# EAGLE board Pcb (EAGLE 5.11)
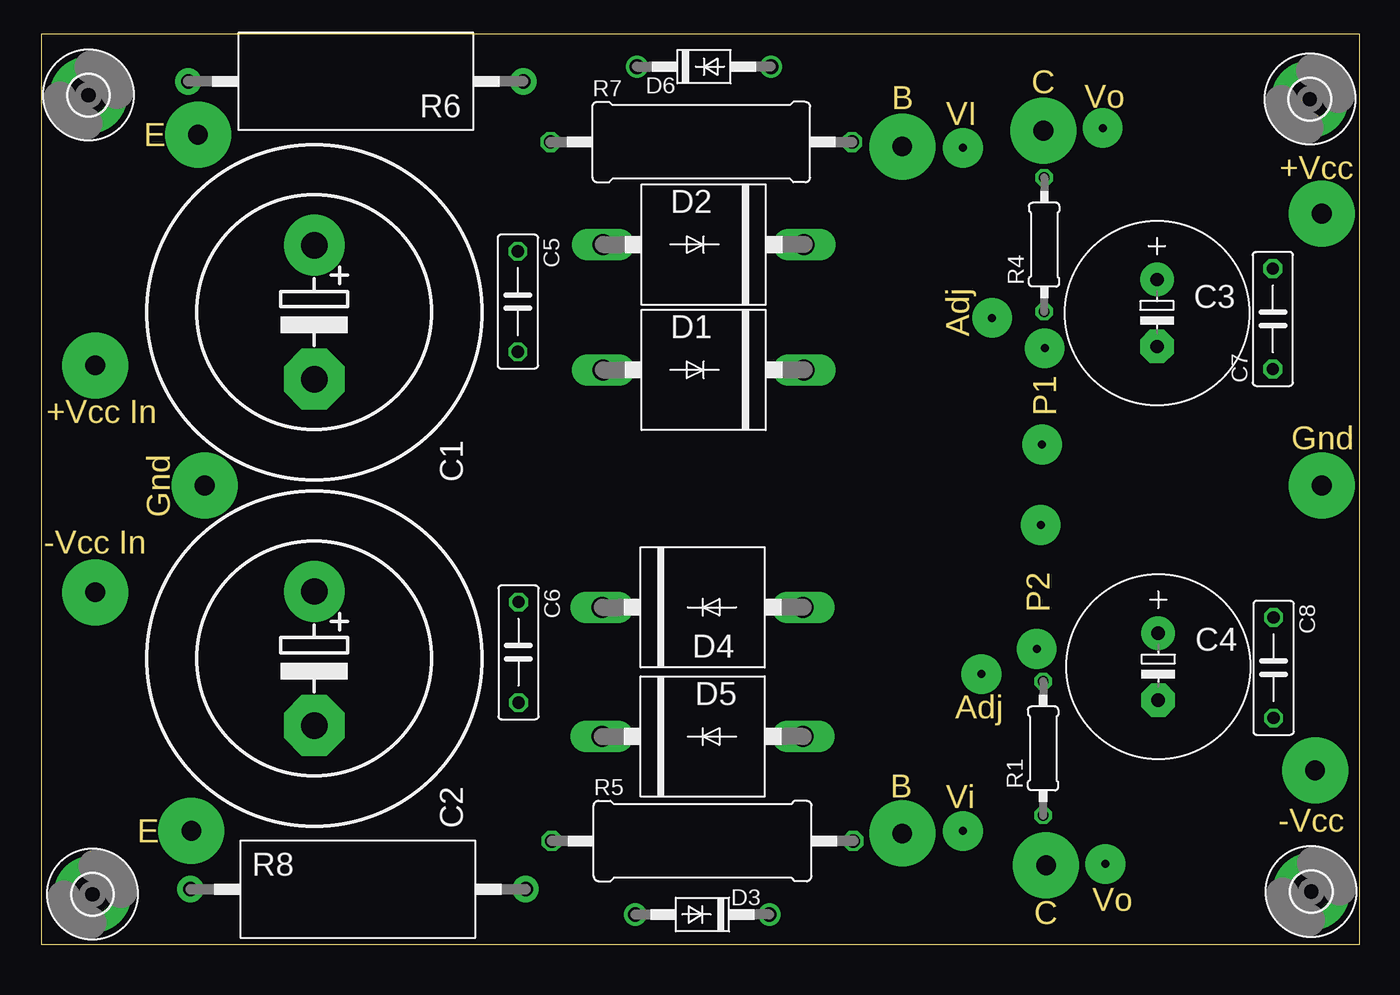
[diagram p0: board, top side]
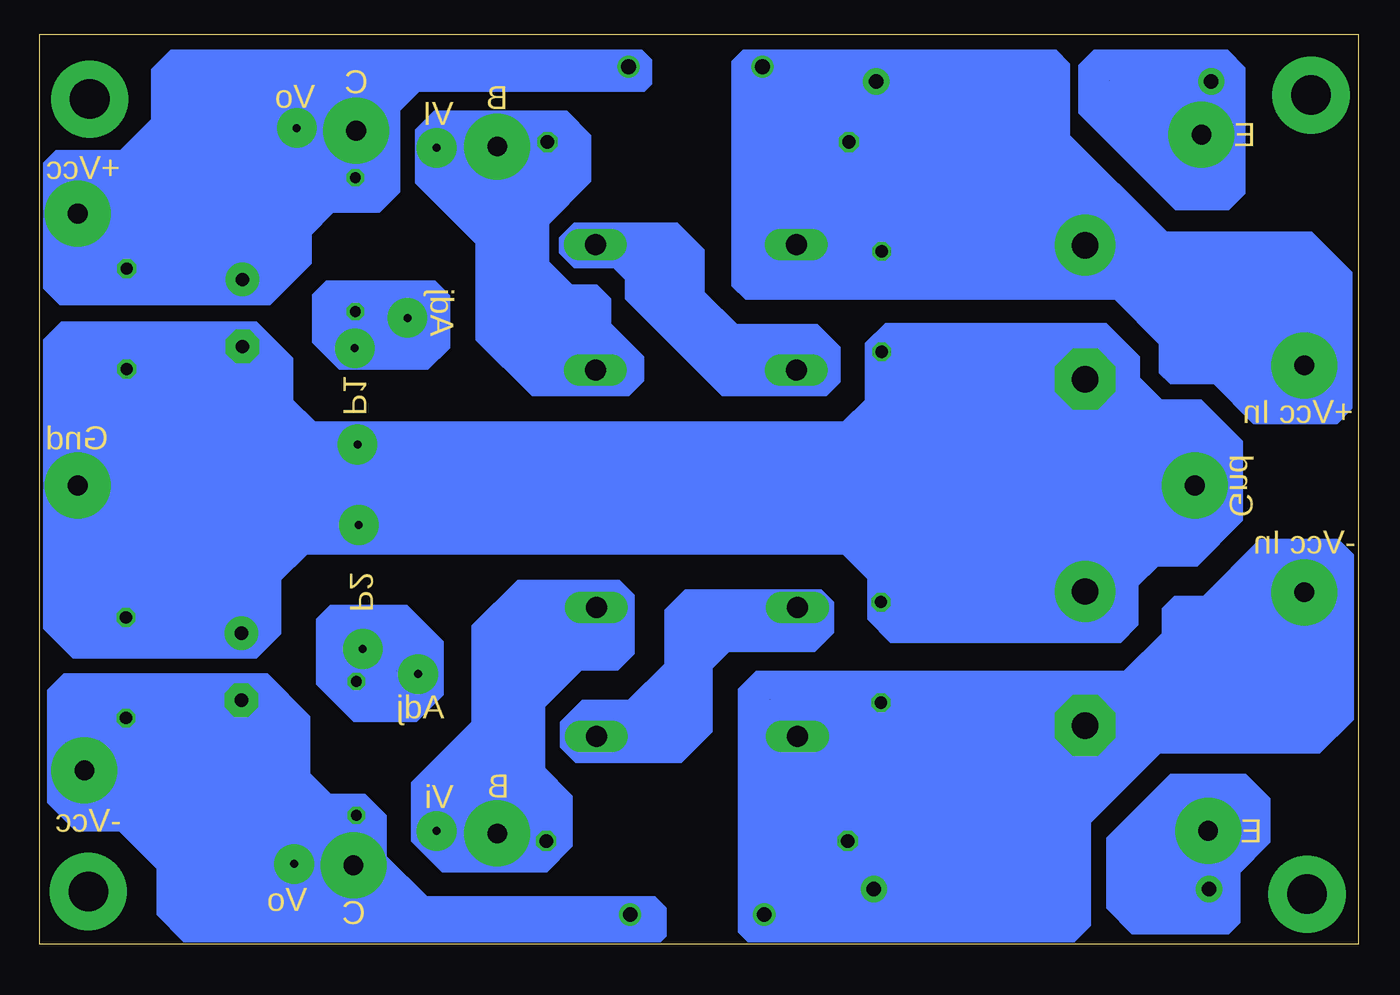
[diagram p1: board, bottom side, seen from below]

Size 100 x 69 mm. Coordinates in mm from the lower left corner, seen from the top.
Outline: 0,0 100,0 100,69 0,69 0,0
Copper layers (1*16): Top 0.035mm / dielectric 1.5mm / Bottom 0.035mm
Design rules "default": minimum track width 10mil, minimum drill 24mil, track to track 8mil, track to pad 8mil, pad to pad 8mil, via to via 8mil, smd to smd 8mil, copper to edge 40mil, drill to drill 8mil, minimum pad ring 10mil, minimum via ring 8mil, stop-mask expansion 4mil, vias tented up to drill 0mil, thermal gap 10mil

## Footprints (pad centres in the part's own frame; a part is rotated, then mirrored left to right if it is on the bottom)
EB25D = drill 2.007 pad 4.597 round: + -5.08,0 | drill 2.007 pad 4.597 octagon: - 5.08,0
E5-13 = drill 1.016 pad 2.54 round: + -2.54,0 | drill 1.016 pad 2.54 octagon: - 2.54,0
C075-032X103 = drill 0.914 octagon: 1 -3.81,0; 2 3.81,0
P6-15 = drill 1.6 long: A 7.62,0; C -7.62,0
DO41-10 = drill 1.118 round: A 5.08,0; C -5.08,0
3,0-PAD = drill 3 pad 5.842 round: B3,0 0,0
0207/10 = drill 0.813 octagon: 1 -5.08,0; 2 5.08,0
0617/22 = drill 1.016 octagon: 1 -11.43,0; 2 11.43,0
AC05 = drill 1.1 pad 2 round: 1 -12.7,0; 2 12.7,0

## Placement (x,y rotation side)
C1  4,7m  [EB25D]  20.72,47.94 270 top
C2  4,7m  [EB25D]  20.72,21.68 270 top
C3  1m  [E5-13]  84.61,47.87 270 top
C4  1m  [E5-13]  84.71,21.06 270 top
C5  100n  [C075-032X103]  36.15,48.74 270 top
C6  100n  [C075-032X103]  36.2,22.14 270 top
C7  100n  [C075-032X103]  93.4,47.43 90 top
C8  100n  [C075-032X103]  93.45,20.97 270 top
D1  1N5408  [P6-15]  50.24,43.56 180 top
D2  1N5408  [P6-15]  50.24,53.06 180 top
D3  1N4007  [DO41-10]  50.14,2.26 180 top
D4  1N5408  [P6-15]  50.16,25.56 0 top
D5  1N5408  [P6-15]  50.16,15.76 0 top
D6  1N4007  [DO41-10]  50.26,66.56 0 top
E$1  [3,0-PAD]  3.6,64.4 0 top
E$2  [3,0-PAD]  3.9,3.8 0 top
E$3  [3,0-PAD]  96.3,4 0 top
E$4  [3,0-PAD]  96.2,64.1 0 top
R1  2k2  [0207/10]  75.98,14.86 90 top
R4  2k2  [0207/10]  76.06,53.06 90 top
R5  10/2W  [0617/22]  50.16,7.84 0 top
R6  0.22/5W  [AC05]  23.86,65.44 0 top
R7  10/2W  [0617/22]  50.06,60.84 0 top
R8  0.22/5W  [AC05]  24.04,4.18 180 top

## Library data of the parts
C1-C8 R1 R4 R5 R7 = resistor
D1-D6 = diode
E$1-E$4 = holes
R6 R8 = resistor-power

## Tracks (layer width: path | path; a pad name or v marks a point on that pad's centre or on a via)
S$1
  Bottom 0.5: 9,38.1 9,32.2 12.3,28.9 15.3,28.9 16.9,27.3 16.9,24.3 18.1,23.1 35.4,23.1 37,24.7 37,27.8 39,29.8 79.8,29.8 81.9,27.7 81.9,23.6 83.6,21.9 97.4,21.9 99.5,24 99.5,31.9 99.5,32.2 99.5,45.8 98.3,47 83.6,47 81,44.4 81,41.2 79.2,39.4 39,39.4 37.2,41.2 37.2,45.5 35.8,46.9 19.2,46.9 16.8,44.5 16.8,42.9 15,41.1 12,41.1 9,38.1
S$2  (via drill 1.5 pad 5)
  other vias: 11.9,61.4 4.1,43.9 4.1,26.7 11.4,8.6
S$3  (via drill 0.6 pad 3)
  other vias: 69.9,60.4 69.9,8.6
S$4
  Bottom 0.5: 47.3,51.9 47.3,66.9 46.6,67.6 23,67.6 22.1,66.7 22.1,61.3 14.6,53.8 3.6,53.8 0.7,50.9 0.7,45 0.7,44.8 0.7,40.7 1.7,39.7 7.9,39.7 10.9,42.7 14.2,42.7 14.9,43.4 14.9,45.6 18.4,49.1 46.4,49.1 47.3,50 47.3,51.9 | 47.3,51.9 45.8,50.4
S$5  (via drill 0.6 pad 3)
  other vias: 75.9,37.9 75.5,22.4 71.3,20.5 75.8,31.8
S$6
  Bottom 0.5: 21,64.7 21,65 21,66.6 20,67.6 10,67.6 8.8,66.4 8.8,57 9.9,55.9 13.8,55.9 21,63.1 21,64.7
S$7
  Bottom 0.5: 60.9,41.8 59.8,41.8 55.4,41.8 54.4,42.8 54.4,44.5 56.9,47 56.9,48.9 57.8,49.8 59.7,49.8 61.6,51.7 61.6,54.7 58.4,57.9 58.4,61.3 60.1,63 70,63 71.3,61.7 71.3,57.8 66.7,53.2 66.7,45.9 62.6,41.8 60.9,41.8 | 60.9,41.8 61,41.9
S$8  (via drill 1.5 pad 5)
  other vias: 65.3,60.5 97.1,55.4 97.1,34.8 12.4,34.8 65.3,8.4 96.6,13.2
S$9  (via drill 1.5 pad 5)
  other vias: 76,61.7 76.2,6
S$10  (via drill 0.6 pad 3)
  other vias: 72.1,47.5
S$11  (via drill 0.6 pad 3)
  other vias: 76.1,45.2
S$12  (via drill 0.6 pad 3)
  other vias: 80.5,61.9 80.7,6.1
S$13
  Bottom 0.5: 55.3,67.6 55,67.6 54.4,67.6 53.8,67 53.8,65.3 54.2,64.9 71.3,64.9 72.9,63.3 72.9,57.1 74.3,55.7 77.8,55.7 79.6,53.9 79.6,51.7 82.6,48.7 98.4,48.7 99.5,49.8 99.5,59.2 98.7,60 93.8,60 91.3,62.5 91.3,66.3 90,67.6 55.3,67.6
S$14
  Bottom 0.5: 49.3,46.8 41.1,46.8 39.5,45.2 39.5,42.7 40.4,41.8 48.2,41.8 55.4,49 55.4,50.5 56.4,51.5 59.4,51.5 60.4,52.5 60.4,53.5 59.4,54.5 51.7,54.5 49.8,52.6 49.8,49.4 47.1,46.7
S$15
  Bottom 0.5: 69.1,49.1 69.1,45.3 70.6,43.8 77.2,43.8 79.1,45.7 79.1,49.2 78.2,50.1 70.1,50.1 69.1,49.1
S$16
  Bottom 0.5: 3.2,30.5 3.9,30.5 7.4,30.5 11.7,26.2 13.9,26.2 14.7,25.4 14.7,23.5 17.7,20.5 45.6,20.5 46.8,19.3 46.8,1 46.2,0.4 21.6,0.4 20.5,1.5 20.5,9.3 15.1,14.7 3,14.7 0.6,17.1 0.6,29.5 1.6,30.5 3.2,30.5
S$17
  Bottom 0.5: 18.9,3.1 18.9,3.7 18.9,8 14.2,12.7 8.6,12.7 6.9,11 6.9,7.8 9.2,5.5 9.2,1.7 9.9,1 17.1,1 18.9,2.8 18.9,3.1
S$18
  Bottom 0.5: 40,25.9 40,23.7 41.3,22.4 47.8,22.4 49.2,21 49.2,16.2 51.4,14 59.3,14 60.3,15 60.3,16.8 58.8,18.3 55.3,18.3 52.4,21.2 52.4,25.3 51,26.7 40.8,26.7 40,25.9
S$19
  Bottom 0.5: 55.1,26.3 55.1,24.9 55.1,22.1 56.2,21 59,21 61.9,18.1 61.9,13.3 59.8,11.2 59.8,7.5 61.6,5.7 69.4,5.7 71.6,7.9 71.6,12.2 67,16.8 67,24.1 63.7,27.4 56.1,27.4 55.1,26.4 55.1,26.3
S$20
  Bottom 2: 14.3,62.6 11.6,62.6 9.8,60.8 9.8,57.4 10.2,57 13.4,57 19.9,63.5 19.9,66.2 19.6,66.5 10.4,66.5 9.9,66 9.9,59.4 10.6,58.7 12.8,58.7 18.1,64 18.1,64.9 11.7,64.9 11.6,65 11.6,60.7 10.9,60 12.4,60 16,63.6 11.8,63.6 11.7,63.5 12.3,63.5 12.7,63.1 12.7,61.3 12,60.6
S$21
  Bottom 0.5: 99.2,17.8 99.2,10.8 97.2,8.8 93.9,8.8 90.9,5.8 90.9,2.3 89,0.4 53,0.4 52.7,0.7 52.7,2.7 53.4,3.4 70.7,3.4 73.9,6.6 73.9,9.7 75.4,11.2 78,11.2 79.7,12.9 79.7,17.2 82.8,20.3 98.1,20.3 99.2,19.2 99.2,17.8 | 99.2,17.8 97.4,19.6
S$22
  Bottom 0.5: 69.6,22.2 69.6,22 69.6,19 71.5,17.1 76.1,17.1 78.8,19.8 78.8,24.6 77.9,25.5 72.2,25.5 69.6,22.9 69.6,22.2
S$23
  Bottom 2: 3,47.4 3,51.9 4,52.9 15.1,52.9 23.1,60.9 23.1,66.2 23.4,66.5 46.1,66.5 46.4,66.2 46.4,50.6 45.9,50.1 17.9,50.1 13.8,46 13.8,43.8 13.7,43.7 10.6,43.7 7.5,40.6 2.1,40.6 1.7,41 1.7,50.4 2.9,51.6 3.3,51.6 3.6,51.3 16.2,51.3 24.8,59.9 24.8,64.8 24.7,64.9 44.8,64.9 44.9,65 44.9,51.8 17.3,51.8 12.5,47 12.5,45.2 12.4,45.1 9.6,45.1 6.8,42.3 3,42.3 2.6,41.9 2.6,49.6 3.2,50.2
  Bottom 3.81: 3.2,50.2 12.6,50.2 12.8,50 12.8,49.5 9.7,46.4 7.5,46.4 4.2,43.1 4.2,46.8 5.9,48.5
S$24
  Bottom 3.81: 23.8,55 21,55 19.7,53.7 42.7,53.7 42.8,53.8 42.8,62.5 43.2,62.9 27.6,62.9 27.1,63.4 27.1,60 24.5,57.4 24.5,56.4 24.7,56.2 39,56.2 39.5,56.7 39.5,59.3 40.4,60.2 29.9,60.2 29.2,59.5 29.1,59.5 28.3,58.7 37.3,58.7 37.5,58.5
S$25
  Bottom 2: 59.5,66.5 54.8,66.5 54.7,66.4 54.7,65.9 71.8,65.9 74,63.7 74,57.4 74.6,56.8 78,56.8 80.5,54.3 80.5,52.2 83,49.7 98.1,49.7 98.4,50 98.4,59 98.3,59.1 93.1,59.1 90.5,61.7 90.5,65.5 89.4,66.6 59.5,66.6
S$26
  Bottom 3.81: 74.5,65.2 75.9,65.2 76,65.3 76,59.1 75.8,58.9 79.3,58.9 82.2,56 82.2,53.8 83.9,52.1 96.2,52.1 96.3,52 96.3,56.6 96.5,56.8 92.2,56.8 88.3,60.7 88.3,64.3 88.1,64.5 79.2,64.5 78.9,64.8 78.9,61.9 79.1,61.7 85.1,61.7 85.1,59.7 90,54.8 | 90,54.8 94.6,54.8 | 90,54.8 85.4,54.8 85.2,55 85.2,55.3 80.7,59.8
S$27
  Bottom 2: 44.2,45 43.5,45 42.8,45.7 41.5,45.7 40.6,44.8 40.6,43.1 40.9,42.8 47.9,42.8 54.5,49.4 54.5,50.9 56,52.4 58.9,52.4 59.3,52.8 59.3,53.4 59.2,53.5 52.2,53.5 50.8,52.1 50.8,49 47.6,45.8 43.3,45.8
S$28
  Bottom 2: 41,44.3 47.3,44.3 52.8,49.8 52.8,50.6 54.3,52.1 53.2,52.1 51.7,50.6
S$29
  Bottom 2: 51.5,51.7 52.7,51.7 53.8,52.8 59.3,52.8 59.5,53
S$30
  Bottom 2: 60.1,43.5 55.4,43.5 55.4,44.1 57.9,46.6 57.9,48.6 58.1,48.8 60.1,48.8 62.7,51.4 62.7,55.1 59.4,58.4 59.4,60.9 60.5,62 69.5,62 70.2,61.3 70.2,58.2 65.6,53.6 65.6,46.2 62.2,42.8 55.9,42.8 55.6,43.1 56.3,43.1 56.9,43.7
  Bottom 3.81: 58.9,45.7 56.9,43.7 60.6,43.7 62.2,45.3 62.4,45.3 63.6,46.5 63.6,54.6 68.6,59.6 61.8,59.6 61.7,59.7 61.7,59.3 63.4,57.6
S$31
  Bottom 3.81: 62.8,48.7 61.3,48.7 60.2,47.6
S$32
  Bottom 2: 17.1,34.8 10.2,34.8 9.9,35.1 9.9,37.5 12.6,40.2 15.6,40.2 17.8,42.4 17.8,43.9 19.8,45.9 35.2,45.9 36.2,44.9 36.2,40.7 38.5,38.4 79.5,38.4 81.6,40.5 81.6,40.6 82,41 82,43.8 84.3,46.1 97.8,46.1 98.5,45.4 98.5,24.2 97.2,22.9 84,22.9 82.9,24 82.9,28.3 80.1,31.1 80.1,30.9 80.4,30.6 38.3,30.6 35.9,28.2 35.9,25.1 35,24.2 18.6,24.2 18,24.8 18,27.6 15.7,29.9 12.6,29.9 9.9,32.6 9.9,34.8 10.1,35
S$33
  Bottom 3.81: 17.1,35.1 12,35.1 11.6,34.7 11.6,34.4 13.8,32.2 16.8,32.2 20.1,28.9 20.1,26.5 20,26.4 33.5,26.4 33.6,26.3 33.6,29.4 36.8,32.6 81.9,32.6 85.1,29.4 85.1,25.1 85,25 96,25 96,43.6 96.5,44.1 85.4,44.1 84.2,42.9 84.2,39.5 81.1,36.4 37.1,36.4 34.3,39.2 34.3,43.2 33.9,43.6 21.1,43.6 20.1,42.6 20.1,42.2 15.9,38 13.3,38 12.5,37.2 12.5,35.9 12.3,35.7 18.2,35.7 18.7,36.2 18.7,36.3 22.7,40.3 31,40.3 31.3,40.6 31.3,38.9 35.3,34.9 35.2,34.9 30.8,30.5 30.8,29.8 23.5,29.8 22.9,29.2 22.9,29.7 19.6,33 19.6,33.3 23.3,37 28.5,37 28.7,37.2 29.2,37.2 31.2,35.2 31.2,35.1 29.1,33 23.7,33 23.6,32.9 23.6,33.8 23.9,34.1 27.9,34.1 28.2,34.4
S$34
  Bottom 3.81: 86.5,33.5 84.1,33.5 83.1,34.5 83.5,34.5 87.3,38.3 87.3,40.4 87,40.7 92,40.7 92.8,41.5 92.8,28.5 93.2,28.1 88,28.1 87.8,27.9 87.8,30.1 86.6,31.3 86.6,34.4 88.2,36 88.2,36.9 89,37.7 90.4,37.7 90.4,36.8 | 90.4,36.8 90.4,30.6 90.8,30.2 90.8,31.6 88.7,33.7 88.7,35.1 90.4,36.8
S$35
  Bottom 2: 87.5,15.5 87.5,18.9 87.3,19.1 87.3,19.3 83.2,19.3 80.7,16.8 80.7,12.3 78.6,10.2 75.9,10.2 74.9,9.2 74.9,6.2 71.2,2.5 53.9,2.5 53.7,2.3 53.7,1.2 88.4,1.2 89.9,2.7 89.9,6.2 93.3,9.6 96.6,9.6 98.3,11.3 98.3,18.8 97.7,19.4 85.4,19.4 85,19 85,18.2 83.8,17
  Bottom 3.81: 83.8,17 83.8,16.8 83.2,16.2 83.2,11.3 80.4,8.5 77.2,8.5 77,8.3 77,6.1 73.4,2.5 86.3,2.5 87.5,3.7 87.5,7.1 92.2,11.8 95.2,11.8 95.7,12.3 95.7,16.9 96.2,17.4 84.5,17.4 84,17.9 85.8,17.9 85.8,10.2 81.7,6.1 77.3,6.1 76.7,5.5 85.2,5.5 86,6.3 86,11 89.1,14.1 89.1,12.2 87.5,10.6 89.3,10.6 93.2,14.5 89.5,14.5 89.5,14 87.7,12.2
S$36
  Bottom 2: 72.7,48.3 72.7,49 70.4,49 70.2,48.8 70.2,45.7 71,44.9 76.9,44.9 78.1,46.1 78.1,48.6 77.6,49.1 73,49.1 72.9,49 71.7,49 71.3,48.6 71.3,46.5 71.4,46.4 76.1,46.4 76.5,46.8 76.5,47.6 71.5,47.6
S$37
  Bottom 2: 73.7,21.4 73.7,24.3 73.8,24.4 72.7,24.4 70.5,22.2 70.5,19.5 72,18 75.6,18 77.9,20.3 77.9,24.2 77.5,24.6 73.6,24.6 72.3,23.3 72.3,22.7 71.9,22.3 71.9,20.3 72.5,19.7 75,19.7 76,20.7 76,23 76.3,23.3 74.7,23.3 74.6,23.4 74.6,20.9
S$38
  Bottom 2: 64.5,9.2 61,9.2 60.8,9.4 60.8,10.9 63,13.1 63,18.3 59.3,22 56.7,22 56.2,22.5 56.2,26.1 56.5,26.4 63.2,26.4 66,23.6 66,16.4 70.6,11.8 70.6,8.3 69,6.7 62,6.7 60.7,8 60.7,9.6 60.6,9.7 61.6,9.7 62.3,10.4
  Bottom 3.81: 62.3,10.4 62.3,8.9 62.4,8.8 67.6,8.8 68.4,9.6 68.4,10.9 64.5,14.8 | 64.5,14.8 64.5,19.7 | 64.5,19.7 64.5,21.8 62.2,24.1 58.6,24.1 57.8,24.9 57.8,23.6 60.6,23.6 64.5,19.7 | 64.5,14.8 64.5,10.3 64.9,9.9
S$39
  Bottom 2: 50.5,23.5 50.5,25.3 50.1,25.7 41.3,25.7 41.1,25.5 41.1,24 41.6,23.5 48.2,23.5 50.1,21.6 50.1,16.7 51.7,15.1 59,15.1 59.2,15.3 59.2,16.6 58.5,17.3 54.8,17.3 51.5,20.6 51.5,24.8 50.5,25.8 41.5,25.8 41,25.3 41,24.6 41.2,24.4 48.9,24.4 50.5,22.8 50.5,18.6 52.1,17 52.1,16.9 52.5,16.5 53.9,16.5 | 58.3,16.5 53.9,16.5 | 53.9,16.5 51,19.4
S$40
  Bottom 2: 39.7,9 39.7,18.6 38.7,19.6 17.3,19.6 14.3,22.6 14,22.6 13.5,23.1 13.5,23.2 13.8,23.5 13.8,25 13.6,25.2 12,25.2 12,24.5 14.9,21.6 14.9,21.7 7.1,29.5 1.9,29.5 1.5,29.1 1.5,17.7 3.6,15.6 15.6,15.6 21.6,9.6 21.6,1.9 22.2,1.3 45.7,1.3 45.8,1.4 45.8,18.8 45,19.6 39.6,19.6 39.5,19.5 39.5,19.1 38.8,18.4
  Bottom 3.81: 38.8,18.4 38.8,17.6 38.6,17.4 16.3,17.4 6.4,27.3 3.7,27.3 3.3,27.7 3.3,18.5 3.8,18 16.6,18 23.1,11.5 23.1,3.5 23.2,3.4 43,3.4 43.4,3 43.4,17.1 43.1,17.4 40.2,17.4 40.1,17.3 40.1,6.2 40.2,6.1 37,6.1 36.9,6.2 36.9,15.9 37.3,16.3 34.6,16.3 33.8,17.1 33.8,3.7 33.7,3.6 30.3,3.6 30.2,3.5 30.2,4.8 30.4,5 30.4,16.2 30.1,16.5 27.1,16.5 26.9,16.7 26.9,4.1 26.7,3.9 25.2,3.9 24.5,4.6 24.5,14.4 23.2,15.7 20.4,15.7 20.3,15.8 18,15.8 12.2,21.6 12.1,21.6 11.2,20.7 6,20.7 6,24.9 3.8,27.1 4.5,27.1 9.4,22.2
S$41
  Bottom 2: 13.6,11.4 13.4,11.4 13.2,11.6 8.8,11.6 7.9,10.7 7.9,8.4 10.1,6.2 10.1,2.4 10.5,2 16.8,2 18,3.2 18,7.5 13.7,11.8 12.1,11.8 11.2,10.9 9.9,10.9 9.5,10.5 9.5,9.2 11.9,6.8 11.9,3.9 11.3,3.3 15.7,3.3 16.2,3.8 16.2,7.3 13.7,9.8 10.9,9.8 10.8,9.9 10.8,9.8 13.4,7.2 13.4,4.9 14.3,4.9 14.4,4.8 14.4,6.9 12.7,8.6 12.7,9 11.8,9.9

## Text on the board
Dimension: C | B | Vo | VI | E | +Vcc | Adj | +Vcc In | P1 | Gnd | Gnd | -Vcc In | P2 | Adj | B | Vi | E | -Vcc | C | Vo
